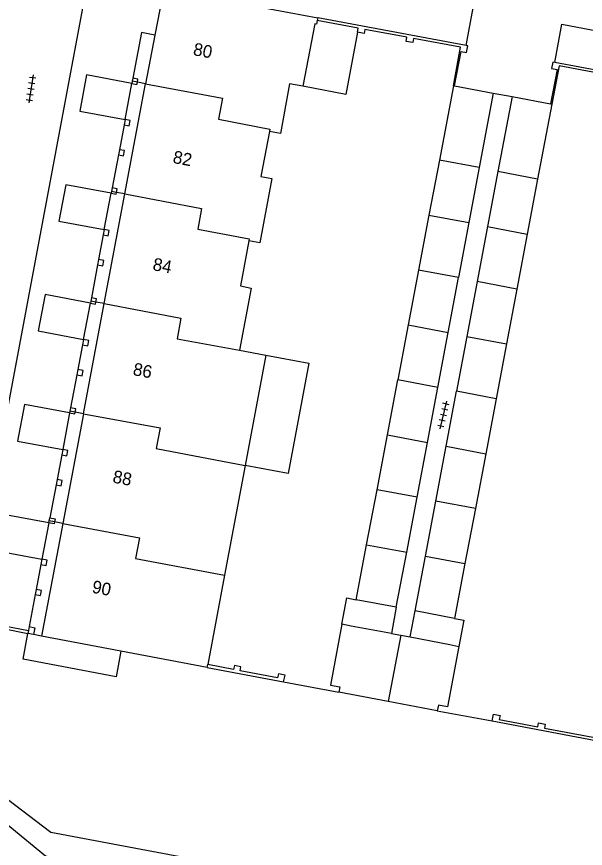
# Model space of a CAD drawing. Extents: x 124000 to 128010, y 398999 to 403000.
# Drawn here: x 126580.2 to 126625.2, y 399120.5 to 399186.3 of the extents above; entities that cross this region are included whole.
import ezdxf

# ---------------------------------------------------------------- set-up
doc = ezdxf.new("R2010")
doc.units = 0
for name, color, linetype in [('gg-afsc-muur', 7, 'Continuous'), ('gg-anno-huisnummerreeks BGT', 7, 'Continuous'), ('gg-bbg-bijgebouw', 7, 'Continuous'), ('gg-bbg-gedigitaliseerde bijgebouw', 7, 'Continuous'), ('gg-bbg-hoofdgebouw', 7, 'Continuous'), ('gg-bbg-luifel en loopbrug', 7, 'Continuous'), ('gg-bbg-onder overbouw', 7, 'Continuous'), ('gg-bbg-pand overbouw', 7, 'Continuous'), ('gg-bbg-pilaar onder overbouw', 7, 'Continuous'), ('gg-bbg-pilaar pand', 7, 'Continuous'), ('gg-bbg-tussenscheiding', 7, 'Continuous'), ('gg-bbg-tussenscheiding niveau 01', 7, 'Continuous'), ('gg-knt-verharding', 7, 'Continuous'), ('gg-kntw-beschoeiing', 7, 'Continuous'), ('gg-kntw-kademuur', 7, 'Continuous'), ('gt-grn-groengrens', 7, 'Continuous'), ('gt-symb-tegel verharding', 7, 'Continuous')]:
    doc.layers.add(name, color=color, linetype=linetype)

# ---------------------------------------------------------------- blocks, each defined once
blk = doc.blocks.new('gt0-TEG1')
at = {"layer": 'gt-symb-tegel verharding'}
for p, q in [((-1.125, 0), (1.125, 0)), ((-0.9, -0.25), (-0.9, 0.25)), ((-0.45, -0.25), (-0.45, 0.25)), ((0, -0.25), (0, 0.25)), ((0.45, -0.25), (0.45, 0.25)), ((0.9, -0.25), (0.9, 0.25))]:
    blk.add_line(p, q, dxfattribs=at)

msp = doc.modelspace()

# ---------------------------------------------------------------- linework, layer by layer
at = {"layer": 'gg-afsc-muur'}
for p, q in [((126615.787, 399183.994), (126604.044, 399186.203)), ((126633.634, 399180.611), (126622.803, 399182.655))]:
    msp.add_line(p, q, dxfattribs=at)
for points in [[(126614.771, 399180.816), (126615.338, 399183.864), (126611.612, 399184.557), (126611.552, 399184.233), (126611.021, 399184.332), (126611.081, 399184.656), (126607.758, 399185.274), (126607.698, 399184.95), (126607.167, 399185.049)], [(126614.866, 399180.798), (126615.373, 399183.521), (126615.806, 399183.441), (126615.905, 399183.972), (126615.787, 399183.994)], [(126622.803, 399182.655), (126622.637, 399182.686), (126622.542, 399182.182), (126622.974, 399182.1), (126622.456, 399179.379)], [(126633.597, 399180.413), (126631.189, 399180.869), (126631.127, 399180.545), (126630.596, 399180.645), (126630.658, 399180.97), (126627.307, 399181.602), (126627.245, 399181.277), (126626.715, 399181.378), (126626.776, 399181.702), (126623.132, 399182.395), (126622.554, 399179.36)], [(126576.393, 399138.924), (126576.829, 399138.834), (126576.764, 399138.521), (126578.696, 399138.17), (126578.751, 399138.477), (126579.267, 399138.392), (126579.215, 399138.076), (126581.14, 399137.697)], [(126581.201, 399138.02), (126581.637, 399137.928), (126581.523, 399137.393)], [(126601.333, 399133.646), (126601.445, 399134.175), (126600.914, 399134.284), (126600.85, 399133.971), (126597.893, 399134.523), (126597.949, 399134.837), (126597.432, 399134.932), (126597.374, 399134.617), (126595.332, 399135.019)], [(126617.839, 399130.561), (126617.939, 399131.072), (126618.459, 399130.979), (126618.403, 399130.664), (126621.443, 399130.081), (126621.512, 399130.402), (126622.032, 399130.295), (126621.968, 399129.982), (126626.084, 399129.214)]]:
    msp.add_lwpolyline(points, dxfattribs=at)
at = {"layer": 'gg-bbg-bijgebouw'}
for p, q in [((126614.771, 399180.816), (126613.658, 399174.931)), ((126614.771, 399180.816), (126614.866, 399180.798)), ((126614.866, 399180.798), (126617.914, 399180.231)), ((126617.914, 399180.231), (126616.804, 399174.338)), ((126619.415, 399179.961), (126618.295, 399174.018)), ((126619.415, 399179.961), (126622.456, 399179.379)), ((126622.554, 399179.36), (126621.434, 399173.427)), ((126622.456, 399179.379), (126622.554, 399179.36)), ((126612.836, 399170.583), (126612.014, 399166.235)), ((126615.985, 399169.99), (126615.166, 399165.641)), ((126617.475, 399169.665), (126616.654, 399165.312)), ((126620.611, 399169.074), (126619.788, 399164.721)), ((126611.192, 399161.887), (126610.37, 399157.539)), ((126613.528, 399156.944), (126614.347, 399161.293)), ((126615.836, 399160.973), (126615.018, 399156.634)), ((126618.969, 399160.383), (126618.149, 399156.044)), ((126608.726, 399148.843), (126609.548, 399153.191)), ((126611.89, 399148.247), (126612.709, 399152.596)), ((126613.379, 399147.937), (126614.199, 399152.286)), ((126617.328, 399151.696), (126616.507, 399147.348)), ((126607.081, 399140.14), (126607.904, 399144.492)), ((126610.251, 399139.542), (126611.071, 399143.895)), ((126611.742, 399139.25), (126612.561, 399143.594)), ((126615.686, 399143.005), (126614.865, 399138.662)), ((126609.861, 399137.474), (126610.61, 399137.333)), ((126610.61, 399137.333), (126611.355, 399137.193)), ((126609.619, 399132.08), (126605.699, 399132.821)), ((126613.495, 399131.349), (126609.619, 399132.08))]:
    msp.add_line(p, q, dxfattribs=at)
for points in [[(126605.95, 399138.195), (126605.052, 399133.389), (126605.779, 399133.253), (126605.699, 399132.821)], [(126609.861, 399137.474), (126606.687, 399138.057), (126605.95, 399138.195)], [(126611.355, 399137.193), (126614.474, 399136.592), (126615.203, 399136.45)], [(126615.203, 399136.45), (126614.305, 399131.651), (126613.578, 399131.787), (126613.495, 399131.349)]]:
    msp.add_lwpolyline(points, dxfattribs=at)
at = {"layer": 'gg-bbg-gedigitaliseerde bijgebouw'}
for p, q in [((126616.804, 399174.338), (126613.658, 399174.931)), ((126621.434, 399173.427), (126618.295, 399174.018)), ((126612.836, 399170.583), (126615.985, 399169.99)), ((126617.475, 399169.665), (126620.611, 399169.074)), ((126615.166, 399165.641), (126612.014, 399166.235)), ((126619.788, 399164.721), (126616.654, 399165.312)), ((126611.192, 399161.887), (126614.347, 399161.293)), ((126615.836, 399160.973), (126618.969, 399160.383)), ((126613.528, 399156.944), (126610.37, 399157.539)), ((126618.149, 399156.044), (126615.018, 399156.634)), ((126609.548, 399153.191), (126612.709, 399152.596)), ((126614.199, 399152.286), (126617.328, 399151.696)), ((126611.89, 399148.247), (126608.726, 399148.843)), ((126616.507, 399147.348), (126613.379, 399147.937)), ((126607.904, 399144.492), (126611.071, 399143.895)), ((126612.561, 399143.594), (126615.686, 399143.005)), ((126610.251, 399139.542), (126607.081, 399140.14)), ((126614.865, 399138.662), (126611.742, 399139.25))]:
    msp.add_line(p, q, dxfattribs=at)
at = {"layer": 'gg-bbg-hoofdgebouw'}
for p, q in [((126591.8, 399188.27), (126591.135, 399184.823)), ((126596.089, 399187.703), (126604.044, 399186.203)), ((126604.044, 399186.203), (126603.999, 399185.974)), ((126597.847, 399159.89), (126599.922, 399159.494)), ((126599.922, 399159.494), (126598.287, 399150.776)), ((126598.287, 399150.776), (126596.656, 399142.078)), ((126596.656, 399142.078), (126595.332, 399135.019)), ((126595.289, 399134.789), (126588.461, 399136.08)), ((126595.289, 399134.789), (126595.332, 399135.019))]:
    msp.add_line(p, q, dxfattribs=at)
for points in [[(126603.999, 399185.974), (126603.943, 399185.694), (126603.815, 399185.719), (126602.85, 399180.772)], [(126602.85, 399180.772), (126601.81, 399180.975), (126601.073, 399177.05), (126600.208, 399177.206)], [(126600.208, 399177.206), (126599.537, 399173.642), (126600.412, 399173.487), (126599.445, 399168.382), (126598.567, 399168.548)], [(126598.567, 399168.548), (126597.918, 399164.973), (126598.763, 399164.792), (126597.847, 399159.89)]]:
    msp.add_lwpolyline(points, dxfattribs=at)
at = {"layer": 'gg-bbg-luifel en loopbrug'}
for p, q in [((126613.658, 399174.931), (126612.836, 399170.583)), ((126616.804, 399174.338), (126615.985, 399169.99)), ((126618.295, 399174.018), (126617.475, 399169.665)), ((126621.434, 399173.427), (126620.611, 399169.074)), ((126612.014, 399166.235), (126611.192, 399161.887)), ((126614.347, 399161.293), (126615.166, 399165.641)), ((126616.654, 399165.312), (126615.836, 399160.973)), ((126619.788, 399164.721), (126618.969, 399160.383)), ((126609.548, 399153.191), (126610.37, 399157.539)), ((126612.709, 399152.596), (126613.528, 399156.944)), ((126614.199, 399152.286), (126615.018, 399156.634)), ((126618.149, 399156.044), (126617.328, 399151.696)), ((126607.904, 399144.492), (126608.726, 399148.843)), ((126611.071, 399143.895), (126611.89, 399148.247)), ((126612.561, 399143.594), (126613.379, 399147.937)), ((126616.507, 399147.348), (126615.686, 399143.005)), ((126610.251, 399139.542), (126609.861, 399137.474)), ((126611.355, 399137.193), (126611.742, 399139.25))]:
    msp.add_line(p, q, dxfattribs=at)
for points in [[(126607.167, 399185.049), (126607.228, 399185.373), (126603.999, 399185.974)], [(126607.167, 399185.049), (126606.25, 399180.137), (126602.85, 399180.772)], [(126589.322, 399181.001), (126585.735, 399181.676), (126585.197, 399178.816), (126588.784, 399178.141)], [(126587.682, 399172.313), (126584.095, 399172.988), (126583.553, 399170.109), (126587.137, 399169.435)], [(126586.039, 399163.618), (126582.455, 399164.292), (126581.913, 399161.411), (126585.494, 399160.737)], [(126599.922, 399159.494), (126603.322, 399158.859), (126601.695, 399150.14), (126598.287, 399150.776)], [(126584.396, 399154.919), (126580.815, 399155.593), (126580.272, 399152.702), (126583.85, 399152.029)], [(126582.75, 399146.214), (126579.172, 399146.887), (126578.631, 399144.015), (126582.207, 399143.342)], [(126605.95, 399138.195), (126606.344, 399140.279), (126607.081, 399140.14)], [(126614.865, 399138.662), (126615.595, 399138.524), (126615.203, 399136.45)]]:
    msp.add_lwpolyline(points, dxfattribs=at)
at = {"layer": 'gg-bbg-onder overbouw'}
for p, q in [((126591.135, 399184.823), (126590.409, 399180.969)), ((126588.768, 399172.253), (126590.409, 399180.969)), ((126587.134, 399163.575), (126588.768, 399172.253)), ((126585.493, 399154.86), (126587.134, 399163.575)), ((126585.493, 399154.86), (126583.859, 399146.181)), ((126583.859, 399146.181), (126582.181, 399137.268)), ((126588.461, 399136.08), (126582.181, 399137.268))]:
    msp.add_line(p, q, dxfattribs=at)
at = {"layer": 'gg-bbg-pand overbouw'}
for p, q in [((126588.784, 399178.141), (126589.322, 399181.001)), ((126588.706, 399177.714), (126588.335, 399175.758)), ((126588.256, 399175.337), (126587.761, 399172.729)), ((126587.137, 399169.435), (126587.682, 399172.313)), ((126587.061, 399169.023), (126586.69, 399167.062)), ((126586.612, 399166.647), (126586.118, 399164.028)), ((126585.494, 399160.737), (126586.039, 399163.618)), ((126585.416, 399160.318), (126585.045, 399158.354)), ((126584.967, 399157.936), (126584.472, 399155.329)), ((126584.396, 399154.919), (126583.85, 399152.029)), ((126583.767, 399151.614), (126583.404, 399149.664)), ((126583.321, 399149.241), (126582.83, 399146.631)), ((126582.75, 399146.214), (126582.207, 399143.342)), ((126582.129, 399142.925), (126581.757, 399140.961)), ((126581.678, 399140.542), (126581.201, 399138.02)), ((126581.201, 399138.02), (126581.14, 399137.697)), ((126581.14, 399137.697), (126581.098, 399137.473))]:
    msp.add_line(p, q, dxfattribs=at)
for points in [[(126591.135, 399184.823), (126590.084, 399185.032), (126589.404, 399181.426)], [(126588.461, 399136.08), (126588.073, 399134.027), (126580.71, 399135.423), (126581.098, 399137.473)]]:
    msp.add_lwpolyline(points, dxfattribs=at)
at = {"layer": 'gg-bbg-pilaar onder overbouw'}
for points in [[(126589.322, 399181.001), (126589.725, 399180.924), (126589.757, 399181.092)], [(126589.757, 399181.092), (126589.805, 399181.349), (126589.404, 399181.426)], [(126588.706, 399177.714), (126589.104, 399177.641), (126589.181, 399178.068), (126588.784, 399178.141)], [(126588.256, 399175.337), (126588.654, 399175.262), (126588.733, 399175.683), (126588.335, 399175.758)], [(126587.682, 399172.313), (126588.079, 399172.237), (126588.106, 399172.377)], [(126588.106, 399172.377), (126588.159, 399172.653), (126587.761, 399172.729)], [(126587.061, 399169.023), (126587.454, 399168.949), (126587.53, 399169.362), (126587.137, 399169.435)], [(126586.612, 399166.647), (126587.022, 399166.57), (126587.101, 399166.984), (126586.69, 399167.062)], [(126586.039, 399163.618), (126586.452, 399163.539), (126586.482, 399163.698)], [(126586.482, 399163.698), (126586.53, 399163.948), (126586.118, 399164.028)], [(126585.416, 399160.318), (126585.845, 399160.239), (126585.923, 399160.658), (126585.494, 399160.737)], [(126584.967, 399157.936), (126585.388, 399157.857), (126585.466, 399158.275), (126585.045, 399158.354)], [(126584.835, 399154.984), (126584.885, 399155.253), (126584.472, 399155.329)], [(126584.396, 399154.919), (126584.809, 399154.843), (126584.835, 399154.984)], [(126583.767, 399151.614), (126584.165, 399151.535), (126584.248, 399151.949), (126583.85, 399152.029)], [(126583.321, 399149.241), (126583.729, 399149.16), (126583.812, 399149.583), (126583.404, 399149.664)], [(126582.83, 399146.631), (126583.244, 399146.552), (126583.197, 399146.306)], [(126583.197, 399146.306), (126583.164, 399146.135), (126582.75, 399146.214)], [(126582.129, 399142.925), (126582.543, 399142.848), (126582.621, 399143.26), (126582.207, 399143.342)], [(126581.678, 399140.542), (126582.093, 399140.464), (126582.171, 399140.883), (126581.757, 399140.961)]]:
    msp.add_lwpolyline(points, dxfattribs=at)
at = {"layer": 'gg-bbg-pilaar pand'}
for p, q in [((126589.354, 399181.168), (126589.322, 399181.001)), ((126589.404, 399181.426), (126589.354, 399181.168)), ((126588.784, 399178.141), (126588.706, 399177.714)), ((126588.335, 399175.758), (126588.256, 399175.337)), ((126587.708, 399172.452), (126587.682, 399172.313)), ((126587.761, 399172.729), (126587.708, 399172.452)), ((126587.137, 399169.435), (126587.061, 399169.023)), ((126586.69, 399167.062), (126586.612, 399166.647)), ((126586.07, 399163.776), (126586.039, 399163.618)), ((126586.118, 399164.028), (126586.07, 399163.776)), ((126585.494, 399160.737), (126585.416, 399160.318)), ((126585.045, 399158.354), (126584.967, 399157.936)), ((126584.472, 399155.329), (126584.423, 399155.062)), ((126584.423, 399155.062), (126584.396, 399154.919)), ((126583.85, 399152.029), (126583.767, 399151.614)), ((126583.404, 399149.664), (126583.321, 399149.241)), ((126582.783, 399146.384), (126582.83, 399146.631)), ((126582.75, 399146.214), (126582.783, 399146.384)), ((126582.207, 399143.342), (126582.129, 399142.925)), ((126581.757, 399140.961), (126581.678, 399140.542))]:
    msp.add_line(p, q, dxfattribs=at)
at = {"layer": 'gg-bbg-tussenscheiding'}
msp.add_line((126610.61, 399137.333), (126609.619, 399132.08), dxfattribs=at)
for points in [[(126590.409, 399180.969), (126596.486, 399179.823), (126596.173, 399178.162), (126600.243, 399177.394), (126600.208, 399177.206)], [(126588.768, 399172.253), (126594.842, 399171.107), (126594.534, 399169.476), (126598.597, 399168.71), (126598.567, 399168.548)], [(126587.134, 399163.575), (126593.205, 399162.43), (126592.897, 399160.799), (126597.847, 399159.89)], [(126585.493, 399154.86), (126591.565, 399153.733), (126591.257, 399152.102), (126598.287, 399150.776)], [(126583.859, 399146.181), (126589.925, 399145.037), (126589.617, 399143.406), (126596.656, 399142.078)]]:
    msp.add_lwpolyline(points, dxfattribs=at)
at = {"layer": 'gg-bbg-tussenscheiding niveau 01'}
for p, q in [((126589.757, 399181.092), (126589.354, 399181.168)), ((126590.409, 399180.969), (126589.757, 399181.092)), ((126588.106, 399172.377), (126587.708, 399172.452)), ((126588.768, 399172.253), (126588.106, 399172.377)), ((126586.482, 399163.698), (126586.07, 399163.776)), ((126587.134, 399163.575), (126586.482, 399163.698)), ((126584.835, 399154.984), (126584.423, 399155.062)), ((126585.493, 399154.86), (126584.835, 399154.984)), ((126583.197, 399146.306), (126582.783, 399146.384)), ((126583.859, 399146.181), (126583.197, 399146.306))]:
    msp.add_line(p, q, dxfattribs=at)
at = {"layer": 'gg-knt-verharding'}
for p, q in [((126585.815, 399189.087), (126576.393, 399138.924)), ((126617.914, 399180.231), (126619.415, 399179.961))]:
    msp.add_line(p, q, dxfattribs=at)
for points in [[(126615.787, 399183.994), (126616.331, 399186.991), (126586.244, 399192.658), (126585.821, 399190.272)], [(126622.803, 399182.655), (126623.35, 399185.692), (126648.549, 399180.899)]]:
    msp.add_lwpolyline(points, dxfattribs=at)
at = {"layer": 'gg-kntw-beschoeiing'}
msp.add_lwpolyline([(126578.996, 399125.563), (126578.936, 399124.779), (126582.896, 399121.736), (126695.8, 399100.513)], dxfattribs=at)
at = {"layer": 'gg-kntw-kademuur'}
for p, q in [((126579.148, 399137.854), (126581.098, 399137.473)), ((126581.523, 399137.393), (126581.098, 399137.473)), ((126582.181, 399137.268), (126581.523, 399137.393)), ((126595.289, 399134.789), (126601.333, 399133.646)), ((126601.333, 399133.646), (126605.699, 399132.821)), ((126613.495, 399131.349), (126617.839, 399130.561)), ((126617.839, 399130.561), (126626.041, 399128.988))]:
    msp.add_line(p, q, dxfattribs=at)
at = {"layer": 'gt-grn-groengrens'}
msp.add_lwpolyline([(126579.161, 399131.587), (126578.169, 399131.203), (126576.802, 399124.502), (126582.49, 399119.877), (126717.58, 399094.355), (126722.431, 399095.972), (126724.333, 399095.654)], dxfattribs=at)

# ---------------------------------------------------------------- block references
at = {"layer": 'gt-symb-tegel verharding'}
for p, rotation in [((126581.331, 399180.581), -98.56758990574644), ((126613.983, 399154.754), 76.82507339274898)]:
    msp.add_blockref('gt0-TEG1', p, dxfattribs=dict(at, rotation=rotation))

# ---------------------------------------------------------------- texts
at = {"layer": 'gg-anno-huisnummerreeks BGT'}
for s, p in [('80', (126594.119, 399183.25)), ('82', (126592.512, 399174.715)), ('84', (126590.916, 399166.234)), ('86', (126589.352, 399157.929)), ('88', (126587.75, 399149.423)), ('90', (126586.109, 399140.708))]:
    msp.add_text(s, height=1, rotation=349.3, dxfattribs=at).set_placement(p)

doc.saveas('drawing.dxf')
